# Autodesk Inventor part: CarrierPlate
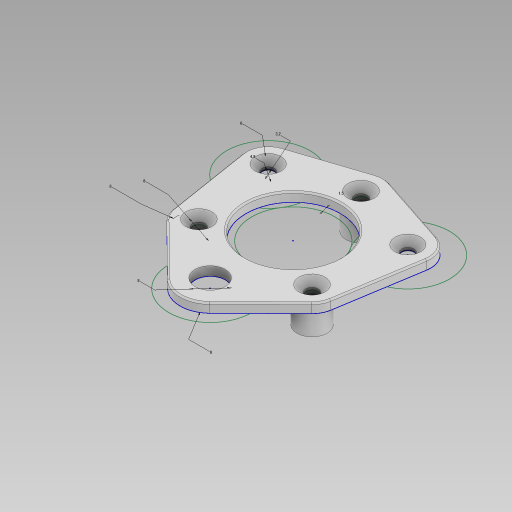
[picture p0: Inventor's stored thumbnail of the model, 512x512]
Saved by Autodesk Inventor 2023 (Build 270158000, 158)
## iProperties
Created: 2024-05
Part Number: CarrierPlate
Material: 一般
Document SubType Name: Modeling
Designer: kumagai
Density: 1 g/cm^3
Appearance: 既定
Author: kumagai
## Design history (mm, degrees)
derived "CoreSketch.ipt"
  sketch "PlanetaryGears"
    geometry: L1 (0, -14)-(0, 14) reference; L2 (-14, 0)-(14, 0) reference; L3 (-32.742, -21.042)-(-37.024, -23.794) reference; C1 r 33 at (0, 0) reference; C2 r 11 at (0, 0) reference; C3 r 11 at (22, 0) reference; C4 r 11 at (-22, 0) reference; C5 r 11 at (0, 22) reference; C6 r 11 at (-18.508, -11.894) reference; C7 r 11 at (18.508, -11.894) reference; C8 r 1.65 at (15, 10) reference; C9 r 1.65 at (-15, 10) reference; C10 r 1.65 at (0, -18) reference; 1 further point
sketch "スケッチ2"
  geometry: L1 (5.621, 27.693)-(19.216, 14.27); L2 (20.924, 10.949)-(24.432, -10.945); L3 (-5.621, 27.693)-(-19.216, 14.27); L4 (-20.924, 10.949)-(-24.432, -10.945); L5 (20.387, -17.592)-(1.88, -23.698); L6 (-1.88, -23.698)-(-20.387, -17.592); C1 r 11 at (0, 22) reference; C2 r 11 at (18.508, -11.894) reference; C3 r 11 at (-18.508, -11.894) reference; C4 r 11 at (0, 0) reference; C5 r 1.6 at (18.508, -11.894); C6 r 1.6 at (-18.508, -11.894); C7 r 12.5 at (0, 0); C8 r 2.4 at (18.508, -11.894); C9 r 2.4 at (-18.508, -11.894); C10 r 4 at (0, 22); C11 r 1.65 at (15, 10) reference; C12 r 1.65 at (-15, 10) reference; C13 r 4 at (15, 10); C14 r 4 at (-15, 10); C15 r 1.65 at (0, -18) reference; C16 r 4 at (0, -18); A1 r 8 centre (0, 22) between (5.621, 27.693) and (-5.621, 27.693); A2 r 6 centre (15, 10) between (20.924, 10.949) and (19.216, 14.27); A3 r 6 centre (18.508, -11.894) between (20.387, -17.592) and (24.432, -10.945); A4 r 6 centre (-18.508, -11.894) between (-24.432, -10.945) and (-20.387, -17.592); A5 r 6 centre (-15, 10) between (-19.216, 14.27) and (-20.924, 10.949); A6 r 6 centre (0, -18) between (-1.88, -23.698) and (1.88, -23.698); 1 further point
  constraints: 15 centre point, 15 coincident, 12 end point, 12 point on circle, 12 tangent, 7 equal radius
  dimensions: "d1" = 1.5 radial gap between concentric circles of C7 C4; "d2" = 3.2 diameter of C5; "d4" = 4.8 diameter of C8; "d5" = 8 diameter of C10; "d6" = 6 radius of A2; "d7" = 6 radius of A3; "d8" = 8 radius of A1; "d9" = 8 diameter of C13
extrude "押し出し1" new body sketch "スケッチ2" distance "d10" = 2.4; taper "d11" = 0 deg
extrude "押し出し2" join sketch "スケッチ2" distance "d12" = 0.2; taper "d13" = 0 deg
extrude "押し出し3" join sketch "スケッチ2" distance "d14" = 6.8; taper "d15" = 0 deg
chamfer "面取り1" distance "d16" = 1.8; stored, may be unused: second distance "d17" = 2, angle "d18" = 45 deg
chamfer "面取り2" distance "d19" = 0.4; stored, may be unused: second distance "d20" = 2, angle "d21" = 45 deg
node "ソリッド1"
